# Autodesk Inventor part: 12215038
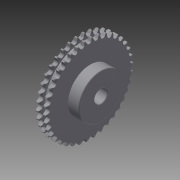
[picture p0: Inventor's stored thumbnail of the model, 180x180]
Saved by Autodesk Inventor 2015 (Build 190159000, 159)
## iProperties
Created: 2018-06
Part Number: 12215038
Material: Generico
Document SubType Name: Modeling
Designer: stagistacad
Density: 1 g/cm^3
Appearance: Default
Author: stagistacad
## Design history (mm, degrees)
sketch "Schizzo1"
  geometry: L1 (-12.701, -12.209)-(-7.301, -12.209); L2 (-14.501, 178.371)-(-14.501, 179.571); L3 (-12.701, 186.871)-(-7.301, 186.871); L4 (-5.501, 179.571)-(-5.501, 178.371); L5 (-14.501, -3.709)-(-5.501, -3.709); L6 (-14.501, -3.709)-(-14.501, -4.909); L7 (-5.501, -4.909)-(-5.501, -3.709); L8 (-14.501, 178.371)-(-5.501, 178.371); L9 (10.999, -4.909)-(10.999, -3.709); L10 (-14.501, 178.371)-(-14.501, -3.709); L11 (-5.501, 178.371)-(-5.501, 174.871); L12 (-5.501, 174.871)-(1.999, 174.871); L13 (-5.501, -0.209)-(1.999, -0.209); L14 (1.999, 178.371)-(10.999, 178.371); L15 (1.999, -3.709)-(10.999, -3.709); L16 (1.999, 178.371)-(1.999, 174.871); L17 (10.999, 178.371)-(10.999, 137.331); L18 (10.999, 137.331)-(33.499, 137.331); L19 (10.999, 37.331)-(33.499, 37.331); L20 (35.499, 135.331)-(35.499, 39.331); L21 (-13.501, 101.831)-(34.499, 101.831); L22 (-13.501, 72.831)-(34.499, 72.831); L23 (-14.501, 102.831)-(-14.501, 71.831); L24 (35.499, 102.831)-(35.499, 71.831); L25 (-13.501, 101.831)-(-13.501, 72.831); L26 (-13.501, 101.831)-(-14.501, 102.831); L27 (-13.501, 72.831)-(-14.501, 71.831); L28 (34.499, 101.831)-(34.499, 72.831); L29 (34.499, 101.831)-(35.499, 102.831); L30 (34.499, 72.831)-(35.499, 71.831); L31 (-5.501, -0.209)-(-5.501, -3.709); L32 (10.999, 37.331)-(10.999, -3.709); L33 (1.999, -0.209)-(1.999, -3.709); L34 (3.799, 186.871)-(9.199, 186.871); L35 (1.999, 178.371)-(1.999, 179.571); L36 (10.999, 179.571)-(10.999, 178.371); L37 (3.799, -12.209)-(9.199, -12.209); L38 (1.999, -3.709)-(1.999, -4.909); L39 (-21.501, 87.331)-(42.499, 87.331); A1 r 15.9 centre (1.399, 179.522) between (-12.701, 186.871) and (-14.501, 179.571); A2 r 15.9 centre (-21.401, 179.522) between (-5.501, 179.571) and (-7.301, 186.871); A3 r 15.9 centre (1.399, -4.861) between (-14.501, -4.909) and (-12.701, -12.209); A4 r 15.9 centre (-21.401, -4.861) between (-7.301, -12.209) and (-5.501, -4.909); A5 r 2 centre (33.499, 135.331) between (35.499, 135.331) and (33.499, 137.331); A6 r 2 centre (33.499, 39.331) between (33.499, 37.331) and (35.499, 39.331); A7 r 15.9 centre (17.899, 179.522) between (3.799, 186.871) and (1.999, 179.571); A8 r 15.9 centre (-4.901, 179.522) between (10.999, 179.571) and (9.199, 186.871); A9 r 15.9 centre (17.899, -4.861) between (1.999, -4.909) and (3.799, -12.209); A10 r 15.9 centre (-4.901, -4.861) between (9.199, -12.209) and (10.999, -4.909); 1 further point
  constraints: 78 end point, 20 point on circle, 10 centre point, 4 point on line
revolve "Rivoluzione1" sketch "Schizzo1" stored, may be unused: angle "d0" = 90 deg
sketch "Schizzo2"
  geometry: L1 (20.163, -104.629)-(-20.163, 104.629); L2 (104.629, 20.163)-(-104.629, -20.163); L3 (-3.5, -3.5)-(3.5, 3.5); L4 (-3.5, 3.5)-(3.5, -3.5); C1 r 15.5 at (0, 0) reference; C2 r 48 at (0, 0) reference; C3 r 5 at (0, 0); C4 r 91.04 at (0, 0); C5 r 1 at (0, 0); C6 r 3.5 at (0, 0); C7 r 1.75 at (0, 0); A1 r 5.131 centre (-77.347, 57.151) between (-78.698, 52.202) and (-73.012, 59.897); A2 r 48.768 centre (41.721, 81.651) between (-3.257, 100.501) and (-5.382, 94.284); A3 r 100.554 centre (0, 0) between (-18.3, 98.875) and (-19.754, 98.594); A4 r 48.768 centre (-58.209, 70.846) between (-14.895, 93.256) and (-18.3, 98.875); A5 r 5.131 centre (-25.934, 92.608) between (-30.041, 89.532) and (-20.828, 92.112); A6 r 48.768 centre (27.713, 87.405) between (-19.754, 98.594) and (-20.828, 92.112); A7 r 100.554 centre (0, 0) between (-34.325, 94.514) and (-35.713, 93.998); A8 r 48.768 centre (-69.077, 60.299) between (-30.041, 89.532) and (-34.325, 94.514); A9 r 5.131 centre (-40.823, 87.076) between (-44.368, 83.366) and (-35.705, 87.428); A10 r 48.768 centre (12.948, 90.774) between (-35.713, 93.998) and (-35.705, 87.428); A11 r 100.554 centre (0, 0) between (-49.413, 87.575) and (-50.697, 86.838); A12 r 48.768 centre (-78.059, 48.107) between (-44.368, 83.366) and (-49.413, 87.575); A13 r 5.131 centre (-54.599, 79.169) between (-57.484, 74.927) and (-49.608, 80.359); A14 r 48.768 centre (-2.169, 91.667) between (-50.697, 86.838) and (-49.608, 80.359); A15 r 100.554 centre (0, 0) between (-63.154, 78.248) and (-64.299, 77.309); A16 r 48.768 centre (-84.913, 34.603) between (-57.484, 74.927) and (-63.154, 78.248); A17 r 5.131 centre (-66.885, 69.103) between (-69.033, 64.443) and (-62.158, 71.098); A18 r 48.768 centre (-17.227, 90.06) between (-64.299, 77.309) and (-62.158, 71.098); A19 r 100.554 centre (0, 0) between (-75.172, 66.786) and (-76.147, 65.672); A20 r 48.768 centre (-89.45, 20.155) between (-69.033, 64.443) and (-75.172, 66.786); A21 r 5.131 centre (-94.433, -18.198) between (-91.707, -22.545) and (-93.518, -13.15); A22 r 48.768 centre (-31.816, 85.996) between (-76.147, 65.672) and (-73.012, 59.897); A23 r 100.554 centre (0, 0) between (-85.139, 53.502) and (-85.917, 52.243); A24 r 48.768 centre (-91.548, 5.157) between (-78.698, 52.202) and (-85.139, 53.502); A25 r 5.131 centre (-85.698, 43.641) between (-86.217, 38.536) and (-81.875, 47.063); A26 r 48.768 centre (-45.536, 79.586) between (-85.917, 52.243) and (-81.875, 47.063); A27 r 100.554 centre (0, 0) between (-92.784, 38.759) and (-93.344, 37.389); A28 r 48.768 centre (-91.148, -9.982) between (-86.217, 38.536) and (-92.784, 38.759); A29 r 5.131 centre (-91.713, 28.94) between (-91.384, 23.82) and (-88.505, 32.945); A30 r 48.768 centre (-58.015, 71.006) between (-93.344, 37.389) and (-88.505, 32.945); A31 r 100.554 centre (0, 0) between (-97.898, 22.959) and (-98.225, 21.515); A32 r 48.768 centre (-88.262, -24.848) between (-91.384, 23.82) and (-97.898, 22.959); A33 r 5.131 centre (-95.225, 13.45) between (-94.058, 8.454) and (-92.72, 17.928); A34 r 48.768 centre (-68.911, 60.489) between (-98.225, 21.515) and (-92.72, 17.928); A35 r 100.554 centre (0, 0) between (-100.341, 6.532) and (-100.427, 5.054); A36 r 48.768 centre (-82.968, -39.037) between (-94.058, 8.454) and (-100.341, 6.532); A37 r 5.131 centre (-96.14, -2.407) between (-94.167, -7.143) and (-94.407, 2.422); A38 r 48.768 centre (-77.927, 48.321) between (-100.427, 5.054) and (-94.407, 2.422); A39 r 100.554 centre (0, 0) between (-100.048, -10.073) and (-99.889, -11.545); A40 r 48.768 centre (-75.411, -52.16) between (-94.167, -7.143) and (-100.048, -10.073); A41 r 48.768 centre (-84.818, 34.836) between (-99.889, -11.545) and (-93.518, -13.15); A42 r 100.554 centre (0, 0) between (-97.026, -26.403) and (-96.626, -27.829); A43 r 48.768 centre (-65.798, -63.861) between (-91.707, -22.545) and (-97.026, -26.403); A44 r 5.131 centre (-90.15, -33.493) between (-86.745, -37.332) and (-90.078, -28.363); A45 r 48.768 centre (-89.395, 20.4) between (-96.626, -27.829) and (-90.078, -28.363); A46 r 100.554 centre (0, 0) between (-91.357, -42.013) and (-90.728, -43.353); A47 r 48.768 centre (-54.389, -73.82) between (-86.745, -37.332) and (-91.357, -42.013); A48 r 5.131 centre (-83.407, -47.875) between (-79.418, -51.101) and (-84.181, -42.802); A49 r 48.768 centre (-91.533, 5.408) between (-90.728, -43.353) and (-84.181, -42.802); A50 r 100.554 centre (0, 0) between (-83.196, -56.476) and (-82.355, -57.695); A51 r 48.768 centre (-41.497, -81.765) between (-79.418, -51.101) and (-83.196, -56.476); A52 r 5.131 centre (-74.39, -60.95) between (-69.924, -63.476) and (-75.988, -56.074); A53 r 48.768 centre (-91.175, -9.731) between (-82.355, -57.695) and (-75.988, -56.074); A54 r 100.554 centre (0, 0) between (-72.765, -69.4) and (-71.735, -70.464); A55 r 48.768 centre (-27.473, -87.48) between (-69.924, -63.476) and (-72.765, -69.4); A56 r 5.131 centre (-63.343, -72.363) between (-58.522, -74.119) and (-65.722, -67.817); A57 r 48.768 centre (-88.33, -24.606) between (-71.735, -70.464) and (-65.722, -67.817); A58 r 100.554 centre (0, 0) between (-60.35, -80.43) and (-59.159, -81.31); A59 r 48.768 centre (-12.699, -90.809) between (-58.522, -74.119) and (-60.35, -80.43); A60 r 5.131 centre (-50.569, -81.802) between (-45.525, -82.74) and (-53.663, -77.709); A61 r 48.768 centre (-83.075, -38.809) between (-59.159, -81.31) and (-53.663, -77.709); A62 r 100.554 centre (0, 0) between (-46.288, -89.266) and (-44.969, -89.938); A63 r 48.768 centre (2.421, -91.661) between (-45.525, -82.74) and (-46.288, -89.266); A64 r 5.131 centre (-36.415, -89.01) between (-31.285, -89.105) and (-40.141, -85.482)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; 2 further points
  constraints: 304 point on circle, 157 centre point, 8 end point, 1 coincident, 3 other
extrude "Estrusione1" cut sketch "Schizzo2" distance "d1" = 100; taper "d2" = 0 deg
node "Solido1"
node "Linea chiusa proiettata1"
